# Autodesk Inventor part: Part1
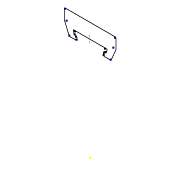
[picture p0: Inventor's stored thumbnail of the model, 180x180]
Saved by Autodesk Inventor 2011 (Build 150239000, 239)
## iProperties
Created: 2010-04
Part Number: Part1
Document SubType Name: Modeling
Designer: Phil
Density: 1 g/cm^3
Author: Phil
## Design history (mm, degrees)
sketch "Sketch1"
  geometry: L1 (11.15, 50.5)-(11.15, 46.304); L2 (-9.064, 41.191)-(-11.07, 45.913); L3 (-7.281, 43.903)-(-6.958, 42.907); L4 (-6.673, 42.7)-(-6.074, 42.7); L5 (-5.78, 42.462)-(-5.568, 41.462); L6 (-5.861, 41.1)-(-8.926, 41.1); L7 (11.07, 45.913)-(9.064, 41.191); L8 (6.958, 42.907)-(7.281, 43.903); L9 (6.074, 42.7)-(6.673, 42.7); L10 (8.926, 41.1)-(5.861, 41.1); L11 (5.568, 41.462)-(5.78, 42.462); L12 (-11.15, 46.304)-(-11.15, 50.5); L13 (7.262, 44.45)-(-7.262, 44.45); L14 (-10.85, 50.8)-(10.85, 50.8); A1 r 1 centre (10.15, 46.304) between (11.07, 45.913) and (11.15, 46.304); A2 r 0.3 centre (10.85, 50.5) between (11.15, 50.5) and (10.85, 50.8); A3 r 0.8 centre (6.521, 44.15) between (7.281, 43.903) and (7.262, 44.45); A4 r 0.8 centre (-6.521, 44.15) between (-7.262, 44.45) and (-7.281, 43.903); A5 r 0.3 centre (-6.673, 43) between (-6.958, 42.907) and (-6.673, 42.7); A6 r 0.15 centre (-8.926, 41.25) between (-9.064, 41.191) and (-8.926, 41.1); A7 r 0.3 centre (-6.074, 42.4) between (-5.78, 42.462) and (-6.074, 42.7); A8 r 0.3 centre (-5.861, 41.4) between (-5.861, 41.1) and (-5.568, 41.462); A9 r 0.3 centre (6.673, 43) between (6.673, 42.7) and (6.958, 42.907); A10 r 0.15 centre (8.926, 41.25) between (8.926, 41.1) and (9.064, 41.191); A11 r 0.3 centre (6.074, 42.4) between (6.074, 42.7) and (5.78, 42.462); A12 r 0.3 centre (5.861, 41.4) between (5.568, 41.462) and (5.861, 41.1); A13 r 1 centre (-10.15, 46.304) between (-11.15, 46.304) and (-11.07, 45.913); A14 r 0.3 centre (-10.85, 50.5) between (-10.85, 50.8) and (-11.15, 50.5); 2 further points
  constraints: 28 end point, 28 point on circle, 14 centre point, 2 tangent, 1 midpoint, 1 parallel, 7 other
